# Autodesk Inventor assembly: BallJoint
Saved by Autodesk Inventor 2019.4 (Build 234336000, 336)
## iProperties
Created: 2020-02
Part Number: BallJoint
Document SubType Name: Assembly
Designer: Administrator
Title: BallJoint v14
Author: Administrator
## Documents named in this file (3)
- c:\worker\convert-fusion-r01\tmp\job-1\5\output\files\e4333473-a38b-4431-9958-ad24a2f67704\BallJoint v14_3.iam
- c:\worker\convert-fusion-r01\tmp\job-1\5\output\files\e4333473-a38b-4431-9958-ad24a2f67704\Component1_1.ipt
- c:\worker\convert-fusion-r01\tmp\job-1\5\output\files\e4333473-a38b-4431-9958-ad24a2f67704\Component2_1.ipt
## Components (2 placed, 2 different names)
1. Component1:1
2. Component2:1
